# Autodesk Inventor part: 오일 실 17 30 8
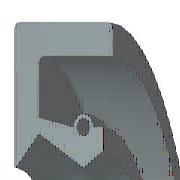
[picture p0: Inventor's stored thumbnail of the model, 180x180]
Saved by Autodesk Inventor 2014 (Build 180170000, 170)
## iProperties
IsCustomPart: 1
Created: 2012-02
Part Number: 오일 실 17 30 8
Material: 고무
Description: 오일-실
Document SubType Name: Modeling
Standard: KS B 2804
Designer: mduedu
Standards Organization: KS
Language: ko-KR
Size Designation: D - 17 30 8
Categories: <MemberInstance><Categories><Category DisplayName="샤프트 부품" InternalName="7f7aeb1f-a693-4053-b835-cee3144e0d98" Mnemonic="SHFT"><Category DisplayName="실링" Intern
Density: 0.93 g/cm^3
Appearance: Rubber - Black - Version 1.1
Author: mduedu
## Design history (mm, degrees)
revolve "본체" stored, may be unused: angle "d17" = 90 deg
revolve "스프링1" stored, may be unused: angle "d18" = 90 deg
body "Solid1"
sketch "스케치1"
  geometry: L1 (0, 15)-(8, 15); L2 (8, 13.25)-(1.75, 13.25); L3 (1.75, 10.25)-(4.9, 8.5); L4 (4.9, 8.5)-(0, 8.5); L5 (0, 0)-(9.586, 0) reference; L6 (4.9, 8.5)-(6.3, 9.375); L7 (0, 18)-(0, -3) reference; L8 (-1.941, 0)-(11.507, 0) reference; L9 (4.2, 10.6)-(1.75, 11.21); L10 (1.75, 11.21)-(1.75, 13.25); L11 (0, 15)-(0, 8.588); L12 (4.9, 8.5)-(0, 8.5); L13 (1.75, 10.25)-(0.152, 8.528); L14 (8, 15)-(8, 13.25); L15 (5.6, 10.6)-(6.3, 10.6); L16 (6.3, 10.6)-(6.3, 9.375); C1 r 0.455 at (4.9, 10.6); A1 r 0.7 centre (4.9, 10.6) between (5.6, 10.6) and (4.2, 10.6); A2 r 0.088 centre (0.088, 8.588) between (0, 8.588) and (0.152, 8.528); 1 further point
  constraints: 28 end point, 5 horizontal alignment, 5 point on line, 4 point on circle, 4 vertical alignment, 3 centre point, 3 tangent, 2 collinear, 2 horizontal, 2 perpendicular, 1 coincident, 1 parallel
  dimensions: "d0" = 30 diameter of L1 L5 (= SD2); "d1" = 1.75 distance of L1.end L2.start (= SD); "d2" = 0.91 diameter of C1 (= SPDI); "d3" = 1.4 diameter of A1 (= SPDA); "d4" = 17 diameter of L3.end L5 (= NND); "d5" = 20.5 diameter of L3.start L5 (= TKDM); "d7" = 22.42 diameter of L9.end L5 (= TKDM + 0.24 x SWDT); "d8" = 1.75 distance between parallel lines of L11 L10 (= SD); "d9" = 4.9 distance from line of L11 C1.centre (= SPDST); "d10" = 21.2 diameter of C1.centre L5 (= HLDM); "d11" = 0.0875 radius of A2 (= 0.25 x LAB); "d12" = 6.3 distance between parallel lines of L11 L16 (= SDI); "d13" = 18.75 diameter of L6.end L5 (= ABDM); "d14" = 8 distance from line of L11 L1.end (= SWDT)
fillet "모깎기1" dims "d6" = 0.3 (= RR)
other parameters: "SD2" = 30 [user parameter; used in 1 equation term], "SWDT" = 8 [user parameter; used in 2 equation terms], "RR" = 0.3 [user parameter; used in 1 equation term], "SD" = 1.75 [user parameter; used in 2 equation terms], "NND" = 17 [user parameter; used in 1 equation term], "SPDA" = 1.4 [user parameter; used in 1 equation term], "SPDI" = 0.91 [user parameter; used in 1 equation term], "TKDM" = 20.5 [user parameter; used in 2 equation terms], "HLDM" = 21.2 [user parameter; used in 1 equation term], "ABDM" = 18.75 [user parameter; used in 1 equation term], "SDI" = 6.3 [user parameter; used in 1 equation term], "SPDST" = 4.9 [user parameter; used in 1 equation term], "LAB" = 0.35 [user parameter; used in 1 equation term], "d15" = 0, "d16" = 0, "d19" = 0
